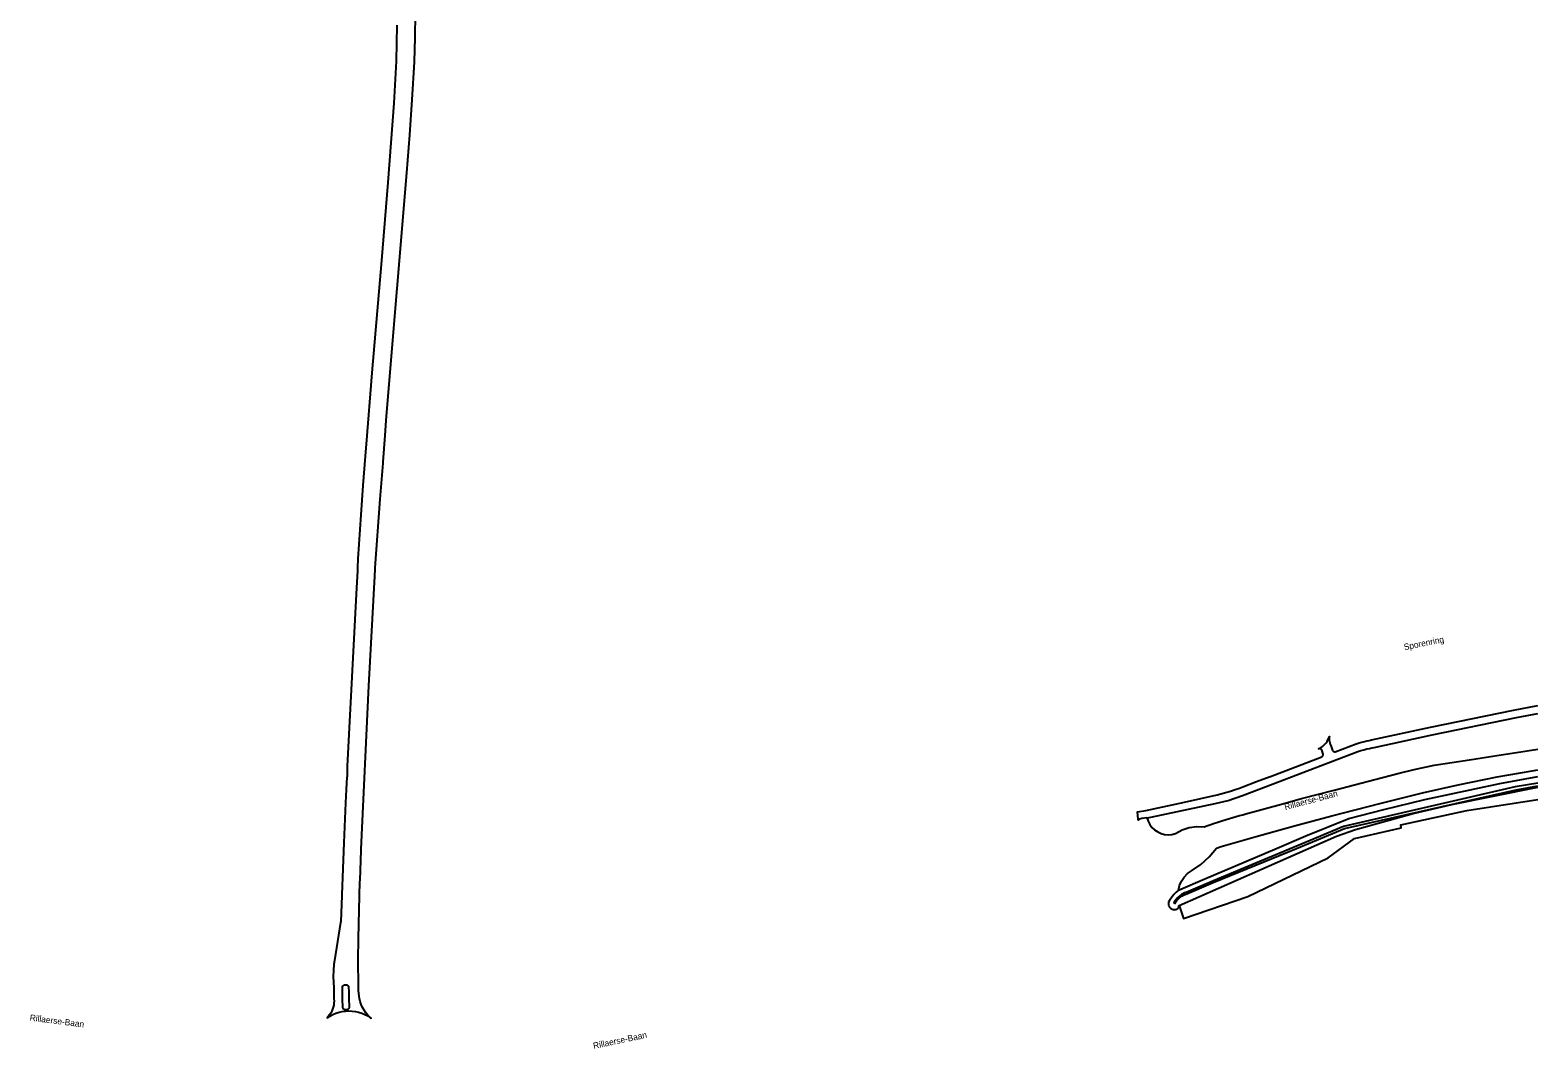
# Model space of a CAD drawing. Extents: x 131000 to 133013, y 393000 to 396501.
# Drawn here: x 132396 to 133000, y 393354 to 393762 of the extents above; entities that cross this region are included whole.
import ezdxf

# ---------------------------------------------------------------- set-up
doc = ezdxf.new("R2010")
doc.units = 0
doc.layers.add('gg-anno-openbare ruimte label', color=7, linetype='Continuous')
doc.layers.add('gx-grn-maaiveld', color=7, linetype='Continuous')

msp = doc.modelspace()

# ---------------------------------------------------------------- linework, layer by layer
at = {"layer": 'gx-grn-maaiveld'}
for points in [[(132542.61, 393764.36), (132542.33, 393750.02), (132541.47, 393733.11), (132539.03, 393701.31), (132536.49, 393670.13), (132532.64, 393625.01), (132530.36, 393596.44), (132530.25, 393594.98), (132529.04, 393579.87), (132527.06, 393550.52), (132527.05, 393550.41), (132526.89, 393547.21), (132526.81, 393545.76), (132526.46, 393538.91), (132522.74, 393467.39), (132522.73, 393463.15), (132522.55, 393463.06), (132522.33, 393458.09), (132522.11, 393452.78), (132521.46, 393436.73), (132520.61, 393415.96), (132520.58, 393415.42), (132520.16, 393405.11), (132520.11, 393404.73), (132517.61, 393389.46), (132517.38, 393388.03), (132517.22, 393385.57), (132517.17, 393383.1), (132517.33, 393378.58), (132517.39, 393377.14), (132517.44, 393374.18), (132517.48, 393373.32), (132517.44, 393372.47), (132517.33, 393371.63), (132517.14, 393370.8), (132516.88, 393369.99), (132516.55, 393369.2), (132516.16, 393368.45), (132515.69, 393367.74), (132515.17, 393367.06), (132514.71, 393366.57), (132515.82, 393367.27), (132516.99, 393367.88), (132518.21, 393368.39), (132519.48, 393368.79), (132520.77, 393369.08), (132522.08, 393369.25), (132523.4, 393369.31), (132524.72, 393369.25), (132526.03, 393369.08), (132527.32, 393368.79), (132528.58, 393368.4), (132529.8, 393367.89), (132530.98, 393367.28), (132532.09, 393366.57), (132532.36, 393366.34), (132531.94, 393366.7), (132531.06, 393367.61), (132530.26, 393368.59), (132529.54, 393369.63), (132528.92, 393370.73), (132528.4, 393371.88), (132527.97, 393373.08), (132527.65, 393374.3), (132527.33, 393377.32), (132527.3, 393379.09), (132527.11, 393389.85), (132527.23, 393398.37), (132527.87, 393421.23), (132527.88, 393421.66), (132528.37, 393433.64), (132528.4, 393434.21), (132531.4, 393499.66), (132533.8, 393543.6), (132533.85, 393544.48), (132533.9, 393545.46), (132534.01, 393546.87), (132535.91, 393574.37), (132537.11, 393588.93), (132537.15, 393589.45), (132538.02, 393599.89), (132538.43, 393605.93), (132538.89, 393612.56), (132546.62, 393705.28), (132547.79, 393720.52), (132548.76, 393734.53), (132549.67, 393749.72), (132549.99, 393759.42), (132550.07, 393769.12)], [(132843.31, 393446.74), (132841.26, 393446.4), (132840.29, 393446.23), (132840.24, 393446.22), (132840.2, 393446.2), (132840.16, 393446.18), (132840.12, 393446.16), (132840.08, 393446.13), (132840.04, 393446.1), (132840.01, 393446.06), (132839.98, 393446.02), (132839.96, 393445.99), (132839.94, 393445.94), (132839.92, 393445.9), (132839.9, 393445.86), (132839.9, 393445.81), (132839.89, 393445.76), (132839.89, 393445.72), (132839.84, 393446.12), (132839.47, 393449.1), (132842.88, 393449.66), (132858.36, 393453.01), (132871.52, 393455.92), (132876.74, 393457.42), (132878.61, 393458.04), (132880.47, 393458.65), (132881.75, 393459.07), (132887.22, 393461.22), (132892.76, 393463.24), (132892.81, 393463.26), (132913.47, 393471.2), (132913.58, 393471.33), (132913.68, 393471.46), (132913.77, 393471.6), (132913.84, 393471.75), (132913.9, 393471.92), (132913.94, 393472.1), (132913.97, 393472.28), (132913.36, 393473.93), (132913.31, 393473.99), (132913.26, 393474.07), (132913.2, 393474.13), (132913.14, 393474.2), (132913.07, 393474.25), (132912.99, 393474.3), (132912.91, 393474.35), (132912.83, 393474.38), (132912.75, 393474.41), (132912.67, 393474.43), (132912.58, 393474.44), (132912.5, 393474.45), (132912.42, 393474.45), (132912.33, 393474.44), (132912.25, 393474.42), (132912.17, 393474.4), (132912.09, 393474.37), (132912.63, 393474.61), (132913.19, 393474.96), (132913.72, 393475.35), (132914.22, 393475.78), (132914.68, 393476.26), (132915.1, 393476.77), (132915.52, 393477.36), (132915.88, 393478), (132916.18, 393478.66), (132916.43, 393479.34), (132916.36, 393478.83), (132916.34, 393478.3), (132916.37, 393477.78), (132916.44, 393477.26), (132916.57, 393476.75), (132916.74, 393476.26), (132917.1, 393475.32), (132917.1, 393475.3), (132917.71, 393473.71), (132917.78, 393473.62), (132917.85, 393473.55), (132917.92, 393473.48), (132918, 393473.42), (132918.07, 393473.37), (132918.13, 393473.33), (132918.2, 393473.3), (132918.3, 393473.26), (132918.4, 393473.23), (132918.5, 393473.21), (132918.61, 393473.19), (132918.71, 393473.19), (132918.82, 393473.19), (132927.23, 393476.36), (132928.33, 393476.73), (132929.44, 393477.07), (132930.56, 393477.36), (132931.49, 393477.57), (132932.42, 393477.75), (132933.36, 393477.91), (132957, 393483.02), (132990.29, 393489.88), (133000, 393491.74)], [(132843.31, 393446.74), (132844.85, 393447), (132870.7, 393452.5), (132875.91, 393453.67), (132881.62, 393455.71), (132893.94, 393460.39), (132917.72, 393469.41), (132927.81, 393473.23), (132929.03, 393473.64), (132930.26, 393474.01), (132931.51, 393474.34), (132932.46, 393474.56), (132933.41, 393474.75), (132934.37, 393474.92), (132957.68, 393479.91), (132991.49, 393486.92), (133000, 393488.51)], [(132843.31, 393446.74), (132843.38, 393446.51), (132843.76, 393445.35), (132844.44, 393444.05), (132845.33, 393442.89), (132846.4, 393441.88), (132847.61, 393441.07), (132848.95, 393440.46), (132850.36, 393440.09), (132851.82, 393439.95), (132853.28, 393440.06), (132854.7, 393440.4), (132857.39, 393441.83), (132860.29, 393442.77), (132863.31, 393443.2), (132866.35, 393443.09), (132866.92, 393443.31), (132868.48, 393443.88), (132870.05, 393444.43), (132871.71, 393444.99), (132873.37, 393445.53), (132875.04, 393446.04), (132876.39, 393446.44), (132877.75, 393446.83), (132879.11, 393447.22), (132880.4, 393447.59), (132881.69, 393447.95), (132882.98, 393448.3), (132897.28, 393452.18), (132905.33, 393454.41), (132918.38, 393457.85), (132934.67, 393462.13), (132944.37, 393464.61), (132950.47, 393466.07), (132958.5, 393467.79), (132972.56, 393469.97), (132982.71, 393471.52), (132995.75, 393473.53), (133000, 393474.19)], [(132855.92, 393417.74), (132856.42, 393419.59), (132857.22, 393421.34), (132858.29, 393422.93), (132859.61, 393424.33), (132861.13, 393425.5), (132864.89, 393428.05), (132868.24, 393431.11), (132871.13, 393434.61), (132873.03, 393435.26), (132887.05, 393439.25), (132902.42, 393443.47), (132917.38, 393447.49), (132936.7, 393452.5), (132953.78, 393456.78), (132968.12, 393459.93), (132983.74, 393463.09), (132997.77, 393465.51), (133000, 393465.89)], [(132855.92, 393417.74), (132866.56, 393422.24), (132894.56, 393434.08), (132906.99, 393439.5), (132924.18, 393446.43), (132938.25, 393450.01), (132954.65, 393454.08), (132984.74, 393460.53), (133000, 393463.3)], [(133000, 393460.63), (132990.86, 393459.07), (132922.06, 393443.22), (132908.8, 393437.56), (132869.99, 393421.46), (132859.05, 393416.84), (132858.38, 393416.59), (132857.73, 393416.28), (132857.11, 393415.92), (132856.52, 393415.5), (132855.97, 393415.04), (132855.44, 393414.51), (132854.96, 393413.93), (132854.53, 393413.31), (132854.15, 393412.66), (132854.54, 393412.36), (132854.91, 393412.98), (132855.34, 393413.56), (132855.82, 393414.1), (132856.35, 393414.6), (132856.88, 393415.01), (132857.44, 393415.38), (132858.03, 393415.7), (132858.65, 393415.97), (132859.28, 393416.19), (132869.9, 393420.84), (132903.29, 393434.36), (132922.44, 393442.37), (132991.27, 393457.98), (133000, 393459.53)], [(132856.18, 393411.56), (132919.31, 393439.31), (132926.89, 393442.05), (132950.08, 393448.47), (132965.5, 393452.02), (133000, 393458.94)], [(132856.18, 393411.56), (132857.99, 393406.4), (132883.76, 393415.18), (132915.96, 393430.67), (132926.54, 393438.36), (132945.26, 393442.69), (132945.06, 393443.86), (132971.56, 393449.64), (133000, 393454.11)], [(132855.92, 393417.74), (132854.99, 393416.92), (132854.14, 393416.03), (132853.36, 393415.06), (132852.87, 393414.35), (132852.41, 393413.62), (132852.01, 393412.85), (132851.96, 393412.65), (132851.93, 393412.45), (132851.93, 393412.24), (132851.93, 393412.03), (132851.96, 393411.83), (132852.01, 393411.63), (132852.07, 393411.43), (132852.16, 393411.24), (132852.25, 393411.06), (132852.37, 393410.89), (132852.5, 393410.72), (132852.64, 393410.57), (132852.79, 393410.44), (132852.96, 393410.32), (132853.14, 393410.21), (132853.32, 393410.12), (132853.51, 393410.05), (132853.71, 393409.99), (132853.91, 393409.95), (132854.11, 393409.93), (132854.32, 393409.93), (132854.52, 393409.94), (132854.73, 393409.97), (132854.93, 393410.02), (132855.12, 393410.09), (132855.3, 393410.18), (132855.48, 393410.28), (132855.65, 393410.39), (132855.81, 393410.53), (132855.96, 393410.67), (132856.18, 393411.56)], [(132522.39, 393379.75), (132522.48, 393379.74), (132522.57, 393379.73), (132522.65, 393379.7), (132522.73, 393379.67), (132522.81, 393379.63), (132522.88, 393379.58), (132522.95, 393379.53), (132523.02, 393379.47), (132523.08, 393379.41), (132523.13, 393379.34), (132523.18, 393379.27), (132523.22, 393379.19), (132523.25, 393379.11), (132523.28, 393379.03), (132523.3, 393378.95), (132523.31, 393378.86), (132523.32, 393378.77), (132523.37, 393377.26), (132523.43, 393374.27), (132523.51, 393370.76), (132523.51, 393370.67), (132523.49, 393370.58), (132523.47, 393370.49), (132523.44, 393370.41), (132523.4, 393370.32), (132523.36, 393370.24), (132523.31, 393370.17), (132523.25, 393370.1), (132523.18, 393370.03), (132523.12, 393369.97), (132523.04, 393369.92), (132522.96, 393369.87), (132522.88, 393369.83), (132522.8, 393369.8), (132522.71, 393369.77), (132522.62, 393369.76), (132522.53, 393369.75), (132522.05, 393369.74), (132521.96, 393369.74), (132521.87, 393369.75), (132521.78, 393369.77), (132521.7, 393369.8), (132521.61, 393369.84), (132521.53, 393369.88), (132521.45, 393369.93), (132521.38, 393369.99), (132521.32, 393370.05), (132521.26, 393370.12), (132521.2, 393370.19), (132521.15, 393370.27), (132521.11, 393370.35), (132521.08, 393370.44), (132521.05, 393370.53), (132521.04, 393370.62), (132521.03, 393370.71), (132520.92, 393374.22), (132520.85, 393377.22), (132520.81, 393378.73), (132520.82, 393378.82), (132520.83, 393378.91), (132520.85, 393379), (132520.88, 393379.09), (132520.92, 393379.17), (132520.96, 393379.25), (132521.01, 393379.33), (132521.07, 393379.4), (132521.13, 393379.47), (132521.2, 393379.53), (132521.27, 393379.58), (132521.35, 393379.63), (132521.43, 393379.67), (132521.52, 393379.7), (132521.61, 393379.73), (132521.7, 393379.74), (132521.79, 393379.75), (132522.31, 393379.76), (132522.39, 393379.75)]]:
    msp.add_lwpolyline(points, dxfattribs=at)

# ---------------------------------------------------------------- texts
at = {"layer": 'gg-anno-openbare ruimte label'}
for s, rotation, p in [('Sporenring', 11.5, (132946.54, 393513.88)), ('Rillaerse-Baan', 14.9, (132898.77, 393449.78)), ('Rillaerse-Baan', 352.8, (132395.39, 393365.44)), ('Rillaerse-Baan', 12, (132621.61, 393354.05))]:
    msp.add_text(s, height=2.5, rotation=rotation, dxfattribs=at).set_placement(p)

doc.saveas('drawing.dxf')
